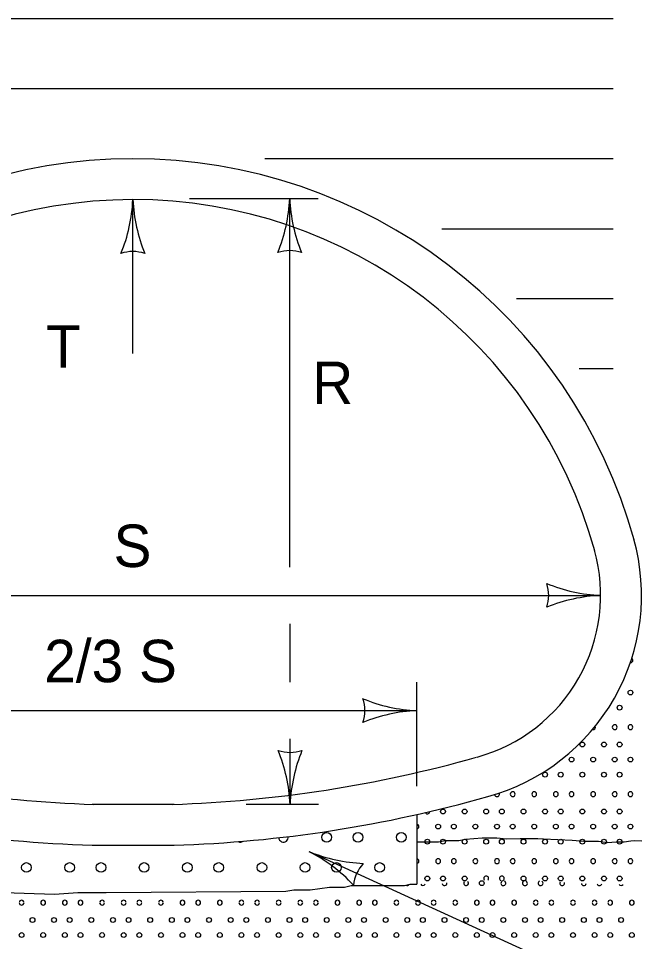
# Model space of a CAD drawing. Extents: x 49991.4 to 50021, y 49987.6 to 50011.4.
# Drawn here: x 50012.817 to 50013.69, y 50001.886 to 50003.19 of the extents above; entities that cross this region are included whole.
import ezdxf

# ---------------------------------------------------------------- set-up
doc = ezdxf.new("R2010")
doc.units = 0
for name, color, linetype in [('Level 1', 7, 'Continuous'), ('Level 2', 7, 'Continuous'), ('Level 3', 7, 'Continuous')]:
    doc.layers.add(name, color=color, linetype=linetype)

msp = doc.modelspace()

# ---------------------------------------------------------------- linework, layer by layer
at = {"layer": 'Level 1'}
for p, q in [((50011.3784, 50003.1896), (50013.657, 50003.1896)), ((50011.4992, 50003.0906), (50013.657, 50003.0906)), ((50013.165, 50002.9916), (50013.657, 50002.9916)), ((50013.4149, 50002.8926), (50013.657, 50002.8926)), ((50013.657, 50002.7936), (50013.5206, 50002.7936)), ((50013.657, 50002.6946), (50013.6089, 50002.6946)), ((50013.3797, 50002.0654), (50013.3797, 50001.9669))]:
    msp.add_line(p, q, dxfattribs=at)
for points in [[(50012.9216, 50002.0798), (50012.9793, 50002.0798), (50013.037, 50002.0798)], [(50013.3797, 50002.0269), (50013.4101, 50002.0269), (50013.4197, 50002.0289), (50013.439, 50002.0289), (50013.4486, 50002.0308), (50013.4718, 50002.0327), (50013.4928, 50002.0325), (50013.5062, 50002.0312), (50013.5258, 50002.0317), (50013.5508, 50002.0317), (50013.5585, 50002.0309), (50013.599, 50002.029), (50013.6153, 50002.0278), (50013.6361, 50002.0277), (50013.6488, 50002.0261), (50013.6612, 50002.0267), (50013.6725, 50002.0267), (50013.6819, 50002.0281), (50013.687, 50002.0285), (50013.6972, 50002.0281)], [(50012.9216, 50002.022), (50012.9793, 50002.022), (50013.037, 50002.022)], [(50012.7821, 50001.9557), (50012.8681, 50001.953), (50012.901, 50001.9552), (50012.9414, 50001.9553), (50013.1947, 50001.9573), (50013.2062, 50001.9592), (50013.2293, 50001.9592), (50013.2564, 50001.963), (50013.2775, 50001.963), (50013.2872, 50001.965), (50013.3315, 50001.965), (50013.3624, 50001.965), (50013.3701, 50001.9669), (50013.3797, 50001.9669)]]:
    msp.add_lwpolyline(points, dxfattribs=at)
for centre, radius in [((50013.6813, 50002.2376), 0.00341), ((50013.666, 50002.2163), 0.00341), ((50013.6134, 50002.1643), 0.00341), ((50013.6439, 50002.1643), 0.00341), ((50013.666, 50002.1643), 0.00341), ((50013.5982, 50002.143), 0.00341), ((50013.6286, 50002.143), 0.00341), ((50013.6286, 50002.143), 0.00341), ((50013.6591, 50002.143), 0.00341), ((50013.6813, 50002.143), 0.00341), ((50013.5608, 50002.1217), 0.00341), ((50013.5829, 50002.1217), 0.00341), ((50013.6134, 50002.1217), 0.00341), ((50013.6439, 50002.1217), 0.00341), ((50013.666, 50002.1217), 0.00341), ((50013.4167, 50002.0697), 0.00341), ((50013.4472, 50002.0697), 0.00341), ((50013.4777, 50002.0697), 0.00341), ((50013.4998, 50002.0697), 0.00341), ((50013.5303, 50002.0697), 0.00341), ((50013.5608, 50002.0697), 0.00341), ((50013.5829, 50002.0697), 0.00341), ((50013.6134, 50002.0697), 0.00341), ((50013.6439, 50002.0697), 0.00341), ((50013.666, 50002.0697), 0.00341), ((50013.2525, 50002.0333), 0.00682), ((50013.2967, 50002.0333), 0.00682), ((50013.3577, 50002.0333), 0.00682), ((50013.3577, 50002.0333), 0.00682), ((50013.4098, 50002.0484), 0.00341), ((50013.432, 50002.0484), 0.00341), ((50013.4624, 50002.0484), 0.00341), ((50013.4624, 50002.0484), 0.00341), ((50013.4929, 50002.0484), 0.00341), ((50013.5151, 50002.0484), 0.00341), ((50013.5455, 50002.0484), 0.00341), ((50013.5455, 50002.0484), 0.00341), ((50013.576, 50002.0484), 0.00341), ((50013.5982, 50002.0484), 0.00341), ((50013.6286, 50002.0484), 0.00341), ((50013.6286, 50002.0484), 0.00341), ((50013.6591, 50002.0484), 0.00341), ((50013.6813, 50002.0484), 0.00341), ((50013.3946, 50002.0271), 0.00341), ((50013.4167, 50002.0271), 0.00341), ((50013.4472, 50002.0271), 0.00341), ((50013.4777, 50002.0271), 0.00341), ((50013.4998, 50002.0271), 0.00341), ((50013.5303, 50002.0271), 0.00341), ((50013.5608, 50002.0271), 0.00341), ((50013.5829, 50002.0271), 0.00341), ((50013.6134, 50002.0271), 0.00341), ((50013.6439, 50002.0271), 0.00341), ((50013.666, 50002.0271), 0.00341), ((50012.8286, 50001.9906), 0.00682), ((50012.8896, 50001.9906), 0.00682), ((50012.9339, 50001.9906), 0.00682), ((50012.9948, 50001.9906), 0.00682), ((50013.0558, 50001.9906), 0.00682), ((50013.1001, 50001.9906), 0.00682), ((50013.161, 50001.9906), 0.00682), ((50013.222, 50001.9906), 0.00682), ((50013.2663, 50001.9906), 0.00682), ((50013.3272, 50001.9906), 0.00682), ((50013.3946, 50001.9751), 0.00341), ((50013.4167, 50001.9751), 0.00341), ((50013.4472, 50001.9751), 0.00341), ((50013.5303, 50001.9751), 0.00341), ((50013.5608, 50001.9751), 0.00341), ((50013.5829, 50001.9751), 0.00341), ((50013.6134, 50001.9751), 0.00341), ((50013.6439, 50001.9751), 0.00341), ((50013.666, 50001.9751), 0.00341), ((50013.4714, 50001.9684), 0.00341), ((50012.8371, 50001.9165), 0.00341), ((50012.8676, 50001.9165), 0.00341), ((50012.8897, 50001.9165), 0.00341), ((50012.9202, 50001.9165), 0.00341), ((50012.9507, 50001.9165), 0.00341), ((50012.9728, 50001.9165), 0.00341), ((50013.0033, 50001.9165), 0.00341), ((50013.0338, 50001.9165), 0.00341), ((50013.0559, 50001.9165), 0.00341), ((50013.0864, 50001.9165), 0.00341), ((50013.1169, 50001.9165), 0.00341), ((50013.139, 50001.9165), 0.00341), ((50013.1695, 50001.9165), 0.00341), ((50013.2, 50001.9165), 0.00341), ((50013.2221, 50001.9165), 0.00341), ((50013.2526, 50001.9165), 0.00341), ((50013.2831, 50001.9165), 0.00341), ((50013.3052, 50001.9165), 0.00341), ((50013.3357, 50001.9165), 0.00341), ((50013.3662, 50001.9165), 0.00341), ((50013.3883, 50001.9165), 0.00341), ((50013.4188, 50001.9165), 0.00341), ((50013.4493, 50001.9165), 0.00341), ((50013.4714, 50001.9165), 0.00341), ((50013.5019, 50001.9165), 0.00341), ((50013.5324, 50001.9165), 0.00341), ((50013.5545, 50001.9165), 0.00341), ((50013.585, 50001.9165), 0.00341), ((50013.6155, 50001.9165), 0.00341), ((50013.6376, 50001.9165), 0.00341), ((50013.6681, 50001.9165), 0.00341), ((50012.8218, 50001.8952), 0.00341), ((50012.8523, 50001.8952), 0.00341), ((50012.8523, 50001.8952), 0.00341), ((50012.8828, 50001.8952), 0.00341), ((50012.9049, 50001.8952), 0.00341), ((50012.9354, 50001.8952), 0.00341), ((50012.9354, 50001.8952), 0.00341), ((50012.9659, 50001.8952), 0.00341), ((50012.988, 50001.8952), 0.00341), ((50013.0185, 50001.8952), 0.00341), ((50013.0185, 50001.8952), 0.00341), ((50013.049, 50001.8952), 0.00341), ((50013.0711, 50001.8952), 0.00341), ((50013.1016, 50001.8952), 0.00341), ((50013.1016, 50001.8952), 0.00341), ((50013.1321, 50001.8952), 0.00341), ((50013.1542, 50001.8952), 0.00341), ((50013.1847, 50001.8952), 0.00341), ((50013.1847, 50001.8952), 0.00341), ((50013.2152, 50001.8952), 0.00341), ((50013.2373, 50001.8952), 0.00341), ((50013.2678, 50001.8952), 0.00341), ((50013.2678, 50001.8952), 0.00341), ((50013.2983, 50001.8952), 0.00341), ((50013.3204, 50001.8952), 0.00341), ((50013.3509, 50001.8952), 0.00341), ((50013.3509, 50001.8952), 0.00341), ((50013.3814, 50001.8952), 0.00341), ((50013.4035, 50001.8952), 0.00341), ((50013.434, 50001.8952), 0.00341), ((50013.434, 50001.8952), 0.00341), ((50013.4645, 50001.8952), 0.00341), ((50013.4866, 50001.8952), 0.00341), ((50013.5171, 50001.8952), 0.00341), ((50013.5171, 50001.8952), 0.00341), ((50013.5476, 50001.8952), 0.00341), ((50013.5697, 50001.8952), 0.00341), ((50013.6002, 50001.8952), 0.00341), ((50013.6002, 50001.8952), 0.00341), ((50013.6307, 50001.8952), 0.00341), ((50013.6528, 50001.8952), 0.00341), ((50013.6833, 50001.8952), 0.00341), ((50013.6833, 50001.8952), 0.00341)]:
    msp.add_circle(centre, radius, dxfattribs=at)
for centre, radius, start, end in [((50012.9793, 50002.2579), 0.7336, 15.4298, 164.6535), ((50012.9793, 50002.2579), 0.6759, 15.4298, 164.6535), ((50013.4024, 50002.3751), 0.2946, 285.2566, 15.6031), ((50013.4024, 50002.3751), 0.2369, 285.2566, 15.6031), ((50013.6813, 50002.2833), 0.00341, 269.531, 0), ((50013.6813, 50002.2834), 0.00341, 0, 53.3071), ((50013.6591, 50002.2376), 0.00341, 305.7447, 350.7661), ((50013.6286, 50002.1887), 0.00341, 256.5554, 24.4764), ((50013.6591, 50002.1888), 0.00341, 0, 180), ((50013.6591, 50002.1887), 0.00341, 180, 0), ((50013.6813, 50002.1888), 0.00341, 0, 180), ((50013.6813, 50002.1887), 0.00341, 180, 0), ((50012.9793, 50003.853), 1.7741, 254.2761, 268.1953), ((50012.9793, 50003.853), 1.7741, 271.8047, 285.8594), ((50013.4929, 50002.0941), 0.00341, 187.8707, 0), ((50013.4929, 50002.0942), 0.00341, 0, 26.0319), ((50013.5151, 50002.0942), 0.00341, 0, 180), ((50013.5151, 50002.0941), 0.00341, 180, 0), ((50013.5455, 50002.0942), 0.00341, 0, 180), ((50013.5455, 50002.0941), 0.00341, 180, 0), ((50013.5455, 50002.0941), 0.00341, 180, 0), ((50013.576, 50002.0942), 0.00341, 0, 180), ((50013.576, 50002.0941), 0.00341, 180, 0), ((50013.5982, 50002.0942), 0.00341, 0, 180), ((50013.5982, 50002.0941), 0.00341, 180, 0), ((50013.6286, 50002.0942), 0.00341, 0, 180), ((50013.6286, 50002.0941), 0.00341, 180, 0), ((50013.6286, 50002.0941), 0.00341, 180, 0), ((50013.6591, 50002.0942), 0.00341, 0, 180), ((50013.6591, 50002.0941), 0.00341, 180, 0), ((50013.6813, 50002.0942), 0.00341, 0, 180), ((50013.6813, 50002.0941), 0.00341, 180, 0), ((50012.9793, 50003.853), 1.8319, 254.2761, 268.1953), ((50012.9793, 50003.853), 1.8319, 271.8047, 285.8594), ((50013.3946, 50002.0697), 0.00341, 208.3453, 357.8709), ((50013.3793, 50002.0484), 0.00341, 276.379, 83.621), ((50013.3793, 50002.0484), 0.00341, 276.379, 83.621), ((50013.1305, 50002.0333), 0.00682, 244.1485, 305.3513), ((50013.1915, 50002.0333), 0.00682, 184.9815, 8.3188), ((50013.3793, 50001.9996), 0.00341, 0, 83.621), ((50013.4098, 50001.9996), 0.00341, 0, 180), ((50013.432, 50001.9996), 0.00341, 0, 180), ((50013.4624, 50001.9996), 0.00341, 0, 180), ((50013.4929, 50001.9996), 0.00341, 0, 180), ((50013.5151, 50001.9996), 0.00341, 0, 180), ((50013.5455, 50001.9996), 0.00341, 0, 180), ((50013.576, 50001.9996), 0.00341, 0, 180), ((50013.5982, 50001.9996), 0.00341, 0, 180), ((50013.6286, 50001.9996), 0.00341, 0, 180), ((50013.6591, 50001.9996), 0.00341, 0, 180), ((50013.6813, 50001.9996), 0.00341, 0, 180), ((50013.3793, 50001.9995), 0.00341, 276.379, 0), ((50013.3793, 50001.9995), 0.00341, 276.379, 0), ((50013.4098, 50001.9995), 0.00341, 180, 0), ((50013.432, 50001.9995), 0.00341, 180, 0), ((50013.4624, 50001.9995), 0.00341, 180, 0), ((50013.4624, 50001.9995), 0.00341, 180, 0), ((50013.4929, 50001.9995), 0.00341, 180, 0), ((50013.5151, 50001.9995), 0.00341, 180, 0), ((50013.5455, 50001.9995), 0.00341, 180, 0), ((50013.5455, 50001.9995), 0.00341, 180, 0), ((50013.576, 50001.9995), 0.00341, 180, 0), ((50013.5982, 50001.9995), 0.00341, 180, 0), ((50013.6286, 50001.9995), 0.00341, 180, 0), ((50013.6286, 50001.9995), 0.00341, 180, 0), ((50013.6591, 50001.9995), 0.00341, 180, 0), ((50013.6813, 50001.9995), 0.00341, 180, 0), ((50013.4777, 50001.9751), 0.00341, 311.9794, 227.1042), ((50013.4998, 50001.9751), 0.00341, 280.5603, 248.0185), ((50013.3662, 50001.9684), 0.00341, 239.6639, 327.9934), ((50013.3883, 50001.9684), 0.00341, 206.9408, 333.0592), ((50013.4188, 50001.9684), 0.00341, 189.4847, 7.016), ((50013.4493, 50001.9684), 0.00341, 148.8555, 47.5996), ((50013.5019, 50001.9684), 0.00341, 104.3697, 64.2091), ((50013.5324, 50001.9684), 0.00341, 106.381, 73.619), ((50013.5545, 50001.9684), 0.00341, 114.8849, 53.1685), ((50013.585, 50001.9684), 0.00341, 155.435, 19.2932), ((50013.6155, 50001.9684), 0.00341, 185.3561, 349.6067), ((50013.6376, 50001.9684), 0.00341, 192.0917, 338.4515), ((50013.6681, 50001.9684), 0.00341, 211.7904, 328.2096), ((50012.8218, 50001.941), 0.00341, 0, 180), ((50012.8218, 50001.9409), 0.00341, 180, 0), ((50012.8523, 50001.941), 0.00341, 0, 180), ((50012.8523, 50001.9409), 0.00341, 180, 0), ((50012.8523, 50001.9409), 0.00341, 180, 0), ((50012.8828, 50001.941), 0.00341, 0, 180), ((50012.8828, 50001.9409), 0.00341, 180, 0), ((50012.9049, 50001.941), 0.00341, 0, 180), ((50012.9049, 50001.9409), 0.00341, 180, 0), ((50012.9354, 50001.941), 0.00341, 0, 180), ((50012.9354, 50001.9409), 0.00341, 180, 0), ((50012.9354, 50001.9409), 0.00341, 180, 0), ((50012.9659, 50001.941), 0.00341, 0, 180), ((50012.9659, 50001.9409), 0.00341, 180, 0), ((50012.988, 50001.941), 0.00341, 0, 180), ((50012.988, 50001.9409), 0.00341, 180, 0), ((50013.0185, 50001.941), 0.00341, 0, 180), ((50013.0185, 50001.9409), 0.00341, 180, 0), ((50013.0185, 50001.9409), 0.00341, 180, 0), ((50013.049, 50001.941), 0.00341, 0, 180), ((50013.049, 50001.9409), 0.00341, 180, 0), ((50013.0711, 50001.941), 0.00341, 0, 180), ((50013.0711, 50001.9409), 0.00341, 180, 0), ((50013.1016, 50001.941), 0.00341, 0, 180), ((50013.1016, 50001.9409), 0.00341, 180, 0), ((50013.1016, 50001.9409), 0.00341, 180, 0), ((50013.1321, 50001.941), 0.00341, 0, 180), ((50013.1321, 50001.9409), 0.00341, 180, 0), ((50013.1542, 50001.941), 0.00341, 0, 180), ((50013.1542, 50001.9409), 0.00341, 180, 0), ((50013.1847, 50001.941), 0.00341, 0, 180), ((50013.1847, 50001.9409), 0.00341, 180, 0), ((50013.1847, 50001.9409), 0.00341, 180, 0), ((50013.2152, 50001.941), 0.00341, 0, 180), ((50013.2152, 50001.9409), 0.00341, 180, 0), ((50013.2373, 50001.941), 0.00341, 0, 180), ((50013.2373, 50001.9409), 0.00341, 180, 0), ((50013.2678, 50001.941), 0.00341, 0, 180), ((50013.2678, 50001.9409), 0.00341, 180, 0), ((50013.2678, 50001.9409), 0.00341, 180, 0), ((50013.2983, 50001.941), 0.00341, 0, 180), ((50013.2983, 50001.9409), 0.00341, 180, 0), ((50013.3204, 50001.941), 0.00341, 0, 180), ((50013.3204, 50001.9409), 0.00341, 180, 0), ((50013.3509, 50001.941), 0.00341, 0, 180), ((50013.3509, 50001.9409), 0.00341, 180, 0), ((50013.3509, 50001.9409), 0.00341, 180, 0), ((50013.3814, 50001.941), 0.00341, 0, 180), ((50013.3814, 50001.9409), 0.00341, 180, 0), ((50013.4035, 50001.941), 0.00341, 0, 180), ((50013.4035, 50001.9409), 0.00341, 180, 0), ((50013.434, 50001.941), 0.00341, 0, 180), ((50013.434, 50001.9409), 0.00341, 180, 0), ((50013.434, 50001.9409), 0.00341, 180, 0), ((50013.4645, 50001.941), 0.00341, 0, 180), ((50013.4645, 50001.9409), 0.00341, 180, 0), ((50013.4866, 50001.941), 0.00341, 0, 180), ((50013.4866, 50001.9409), 0.00341, 180, 0), ((50013.5171, 50001.941), 0.00341, 0, 180), ((50013.5171, 50001.9409), 0.00341, 180, 0), ((50013.5171, 50001.9409), 0.00341, 180, 0), ((50013.5476, 50001.941), 0.00341, 0, 180), ((50013.5476, 50001.9409), 0.00341, 180, 0), ((50013.5697, 50001.941), 0.00341, 0, 180), ((50013.5697, 50001.9409), 0.00341, 180, 0), ((50013.6002, 50001.941), 0.00341, 0, 180), ((50013.6002, 50001.9409), 0.00341, 180, 0), ((50013.6002, 50001.9409), 0.00341, 180, 0), ((50013.6307, 50001.941), 0.00341, 0, 180), ((50013.6307, 50001.9409), 0.00341, 180, 0), ((50013.6528, 50001.941), 0.00341, 0, 180), ((50013.6528, 50001.9409), 0.00341, 180, 0), ((50013.6833, 50001.941), 0.00341, 0, 180), ((50013.6833, 50001.9409), 0.00341, 180, 0), ((50013.6833, 50001.9409), 0.00341, 180, 0)]:
    msp.add_arc(centre, radius, start, end, dxfattribs=at)
at = {"layer": 'Level 3'}
for p, q in [((50012.9788, 50002.7165), (50012.9788, 50002.9338)), ((50013.0588, 50002.9352), (50013.2403, 50002.9352)), ((50013.2003, 50002.4149), (50013.2003, 50002.9352)), ((50012.3194, 50002.3749), (50013.6393, 50002.3749)), ((50013.2003, 50002.3349), (50013.2003, 50002.2521)), ((50013.3797, 50002.1054), (50013.3797, 50002.2522)), ((50012.5767, 50002.2122), (50013.3797, 50002.2122)), ((50013.2008, 50002.0798), (50013.2008, 50002.1722)), ((50013.1387, 50002.0798), (50013.2408, 50002.0798)), ((50014.235, 50001.5519), (50013.228, 50002.0128))]:
    msp.add_line(p, q, dxfattribs=at)
for centre, radius, start, end in [((50012.7567, 50002.943), 0.2223, 337.456, 357.6395), ((50013.2116, 50002.9453), 0.233, 182.8273, 202.0772), ((50012.9676, 50002.9466), 0.233, 337.9228, 357.1727), ((50013.4224, 50002.9443), 0.2223, 182.3605, 202.544), ((50013.2003, 50002.8069), 0.0548, 72.1388, 107.8612), ((50012.9788, 50002.8056), 0.0548, 72.1388, 107.8612), ((50013.6484, 50002.597), 0.2223, 247.456, 267.6395), ((50013.5111, 50002.3749), 0.0548, 342.1388, 17.8612), ((50013.6508, 50002.1422), 0.233, 92.8273, 112.0772), ((50013.3889, 50002.4343), 0.2223, 247.456, 267.6395), ((50013.2515, 50002.2122), 0.0548, 342.1388, 17.8612), ((50013.3912, 50001.9795), 0.233, 92.8273, 112.0772), ((50012.9786, 50002.0706), 0.2223, 2.3605, 22.544), ((50013.2008, 50002.208), 0.0548, 252.1388, 287.8612), ((50013.4335, 50002.0683), 0.233, 157.9228, 177.1727), ((50013.1272, 50001.8146), 0.2223, 42.8606, 63.0441), ((50013.3144, 50002.2292), 0.233, 248.2319, 267.4817), ((50013.3446, 50001.9594), 0.0548, 137.5434, 173.2657)]:
    msp.add_arc(centre, radius, start, end, dxfattribs=at)

# ---------------------------------------------------------------- texts
at = {"layer": 'Level 2'}
for s, p in [('T', (50012.8563, 50002.6964)), ('R', (50013.232, 50002.645)), ('S', (50012.9516, 50002.4149)), ('2/3 S', (50012.8537, 50002.2522))]:
    msp.add_text(s, height=0.06, dxfattribs=at).set_placement(p)

doc.saveas('drawing.dxf')
